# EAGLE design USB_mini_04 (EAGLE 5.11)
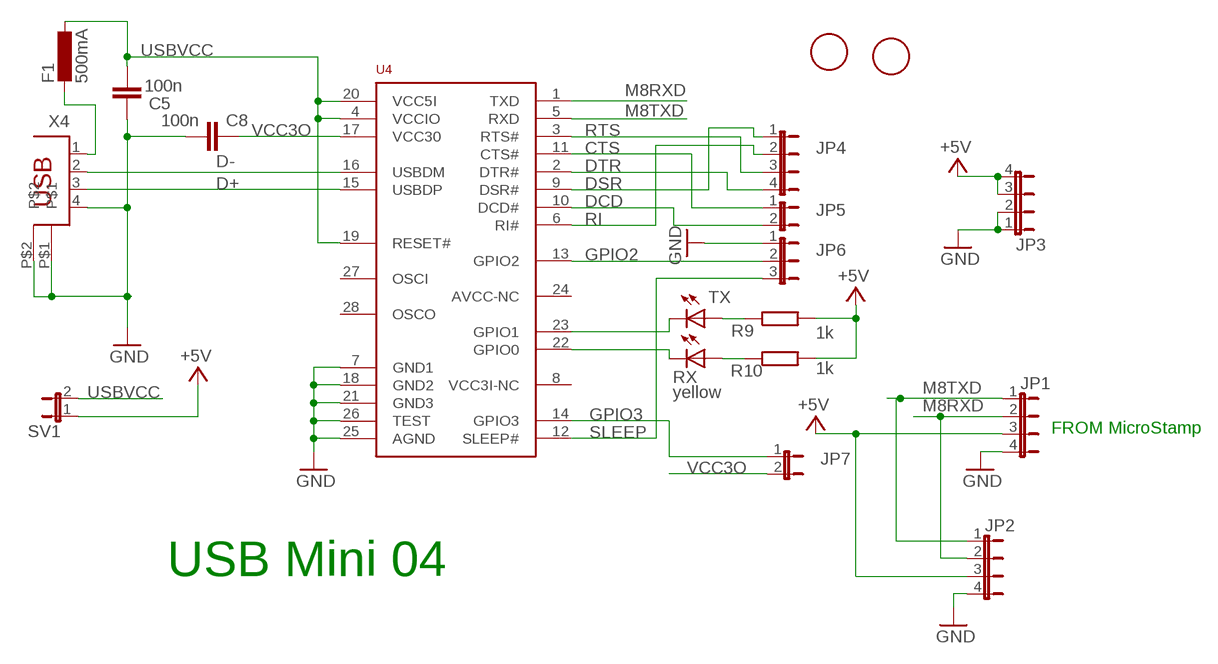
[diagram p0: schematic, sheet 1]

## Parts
C5  100n  C-EUC0805  [C0805]
C8  100n  C-EUC0805  [C0805]
F1  500mA  L-EUL1812  [L1812]
JP1  JP4E  [JP4]
JP2  JP4E  [JP4]
JP3  JP4E  [JP4]
JP4  JP4E  [JP4]
JP5  JP1E  [JP1]
JP6  JP2E  [JP2]
JP7  JP1E  [JP1]
R9  1k  R-EU_R0805  [R0805]
R10  1k  R-EU_R0805  [R0805]
RX  yellow  LEDCHIPLED_0805  [CHIPLED_0805]
SV1  JP1E  [JP1]
TX  yellow  LEDCHIPLED_0805  [CHIPLED_0805]
U4  FT232RL  [SSOP28]
U$1  FIDUCIALMOUNT  [FIDUCIA-MOUNT]
U$2  FIDUCIALMOUNT  [FIDUCIA-MOUNT]
X4  PN61729  [PN61729]

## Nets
+5V [power]: JP1.3 JP2.3 JP3.3 JP3.4 R9.2 R10.2 SV1.1
CTS: JP5.1 U4.11(CTS#)
D+: U4.15(USBDP) X4.3
D-: U4.16(USBDM) X4.2
DCD: JP5.2 U4.10(DCD#)
DSR: JP4.1 U4.9(DSR#)
DTR: JP4.4 U4.2(DTR#)
GND [usbvcc]: C5.2 C8.1 JP1.4 JP2.4 JP3.1 JP3.2 JP6.1 U4.7(GND1) U4.18(GND2) U4.21(GND3) U4.25(AGND) U4.26(TEST) X4.4 X4.P$1 X4.P$2
GPIO2: JP6.2 U4.13(GPIO2)
GPIO3: JP7.1 U4.14(GPIO3)
M8RXD: JP1.2 JP2.2 U4.1(TXD)
M8TXD: JP1.1 JP2.1 U4.5(RXD)
N$2 [usbvcc]: F1.2 X4.1
N$32: TX.C U4.23(GPIO1)
N$34: RX.C U4.22(GPIO0)
N$35: R9.1 TX.A
N$36: R10.1 RX.A
RI: JP4.2 U4.6(RI#)
RTS: JP4.3 U4.3(RTS#)
SLEEP: JP6.3 U4.12(SLEEP#)
USBVCC [usbvcc]: C5.1 F1.1 SV1.2 U4.4(VCCIO) U4.19(RESET#) U4.20(VCC5I)
VCC3O: C8.2 JP7.2 U4.17(VCC30)
Unconnected: U4.8(VCC3I-NC) U4.24(AVCC-NC) U4.27(OSCI) U4.28(OSCO)

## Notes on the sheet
- FROM MicroStamp
- USB Mini 04

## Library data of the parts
C5 C8 = rcl:C-EU: CAPACITOR, European symbol
F1 = rcl:L-EU: INDUCTOR, European symbol
JP1-JP4 = jumper:JP4E: JUMPER
JP5 JP7 SV1 = jumper:JP1E: JUMPER
JP6 = jumper:JP2E: JUMPER
R9 R10 = rcl:R-EU_: RESISTOR, European symbol
RX TX = led:LED: LED
U4 = SmartPrj:FT232RL
U$1 U$2 = SmartPrj:FIDUCIALMOUNT
X4 = SmartPrj:PN61729: BERG USB connector

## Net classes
0 default: width 0.254 mm, clearance 0.254 mm
1 power: width 0.61 mm, clearance 0.254 mm
3 usbvcc: width 0.356 mm, clearance 0.254 mm

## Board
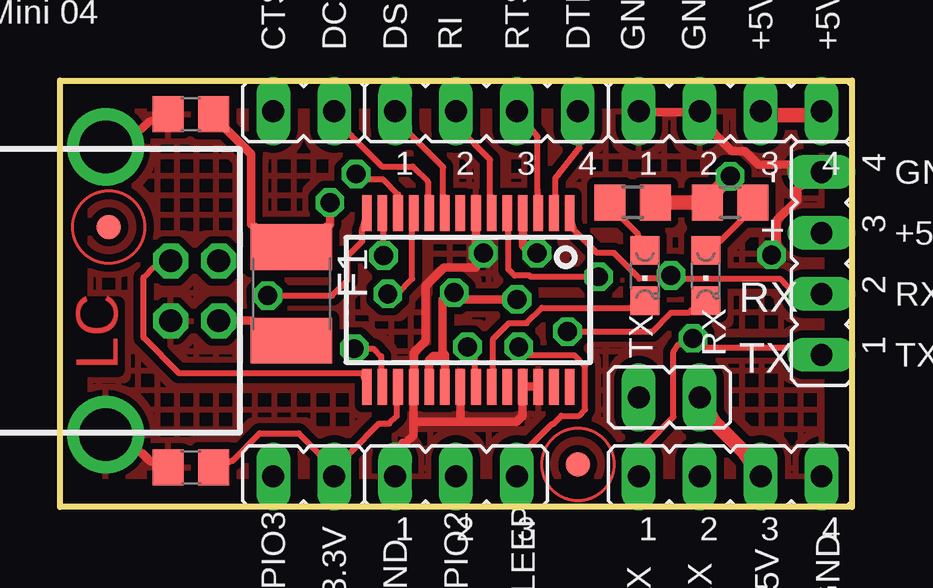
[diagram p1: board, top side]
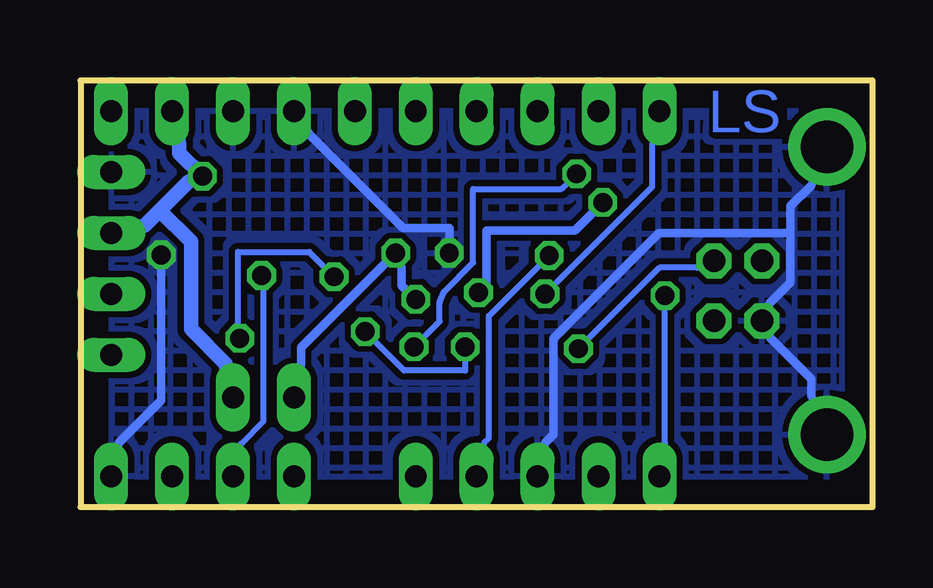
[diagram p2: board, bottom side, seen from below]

Size 33.02 x 17.78 mm. Coordinates in mm from the lower left corner, seen from the top.
Outline: 0,0 0,17.78 33.02,17.78 33.02,0 0,0
Copper layers (1*16): Top 0.035mm / dielectric 1.5mm / Bottom 0.035mm
Design rules "default": minimum track width 10mil, minimum drill 31mil, track to track 10mil, track to pad 10mil, pad to pad 10mil, via to via 16mil, smd to smd 10mil, copper to edge 40mil, drill to drill 10mil, minimum pad ring 10mil, minimum via ring 8mil, stop-mask expansion 4mil, vias tented up to drill 0mil, thermal gap 10mil

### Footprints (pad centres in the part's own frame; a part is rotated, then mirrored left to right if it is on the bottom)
C0805 = smd 1.3 x 1.5: 1 -0.95,0; 2 0.95,0
L1812 = smd 1.9 x 3.4: 1 -1.95,0; 2 1.95,0
JP4 = drill 0.914 long: 1 -3.81,0; 2 -1.27,0; 3 1.27,0; 4 3.81,0
JP1 = drill 0.914 long: 1 0,-1.27; 2 0,1.27
JP2 = drill 0.914 long: 1 -2.54,0; 2 0,0; 3 2.54,0
R0805 = smd 1.3 x 1.5: 1 -0.95,0; 2 0.95,0
CHIPLED_0805 = smd 1.2 x 1.2: A 0,-1.05; C 0,1.05
SSOP28 = smd 0.4 x 1.5: 1 -4.225,-3.625; 2 -3.575,-3.625; 3 -2.925,-3.625; 4 -2.275,-3.625; 5 -1.625,-3.625; 6 -0.975,-3.625; 7 -0.325,-3.625; 8 0.325,-3.625; 9 0.975,-3.625; 10 1.625,-3.625; 11 2.275,-3.625; 12 2.925,-3.625; 13 3.575,-3.625; 14 4.225,-3.625; 15 4.225,3.625; 16 3.575,3.625; 17 2.925,3.625; 18 2.275,3.625; 19 1.625,3.625; 20 0.975,3.625; 21 0.325,3.625; 22 -0.325,3.625; 23 -0.975,3.625; 24 -1.625,3.625; 25 -2.275,3.625; 26 -2.925,3.625; 27 -3.575,3.625; 28 -4.225,3.625
FIDUCIA-MOUNT = smd 1.016 x 1.016: P$1 0,0
PN61729 = drill 0.95 octagon: 1 1.25,4.71; 2 -1.25,4.71; 3 -1.25,2.71; 4 1.25,2.71 | drill 2.2 round: P$1 -6,0; P$2 6,0

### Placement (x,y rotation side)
C5  5.46,16.38 180 top
C8  5.46,1.65 0 top
F1  9.65,8.89 270 top
JP1  31.75,10.16 90 top
JP2  27.94,1.27 0 top
JP3  27.94,16.51 0 top
JP4  17.78,16.51 0 top
JP5  10.16,16.51 270 top
JP6  16.51,1.27 0 top
JP7  10.16,1.27 270 top
R9  23.88,12.7 0 top
R10  27.94,12.7 180 top
RX  26.92,9.65 180 top
SV1  25.4,4.57 90 top
TX  24.38,9.65 180 top
U4  17.02,8.64 180 top
U$1  2.03,11.68 0 top
U$2  21.59,1.78 0 top
X4  1.91,9.02 270 top

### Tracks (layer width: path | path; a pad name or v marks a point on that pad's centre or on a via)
+5V  (via drill 0.79)
  Top 0.61: JP2.3 28.52,2.29 27.3,3.5 SV1.1 | R9.2 R10.2 27.28,13.13 v27.94,13.79 | JP3.4 31.06,16.33 29.9,16.33 JP3.3
  Bottom 0.61: JP3.3 28.91,15.11 28.91,14.76 v27.94,13.79 28.52,13.56 29.72,12.37 | 29.72,12.37 30.35,11.73 JP1.3 | SV1.1 26.98,5.97 28.42,7.42 28.42,11.07 29.72,12.37
CTS  (via drill 0.79)
  Top 0.254: v13.66,8.89 14.05,8.89 14.68,9.53 14.68,11.53 U4.11
  Bottom 0.254: v13.66,8.89 9.2,13.36 9.2,15.11 JP5.1
D+
  Top 0.254: U4.15 12.6,5.59 4.95,5.59 3.48,7.06 3.48,9.58 3.89,9.98 X4.3
D-  (via drill 0.79)
  Top 0.254: v12.27,6.6 13.07,6.6 13.39,6.29 13.39,5.74 U4.16
  Bottom 0.254: v12.27,6.6 8.89,9.98 7.34,9.98 X4.2
DCD
  Top 0.254: U4.10 15.34,13.01 15.34,13.56 14.71,14.2 13.44,14.2 12.14,15.49 12.12,15.49 JP5.2
DSR
  Top 0.254: U4.9 15.98,13.01 15.98,14.17 15.37,14.78 14.66,15.49 JP4.1
DTR
  Top 0.254: U4.2 20.65,13.01 20.65,13.72 21.67,14.99 JP4.4
GND  (via drill 0.79)
  Top 0.356: JP3.1 24.82,16.46 25.98,16.46 JP3.2 27.36,15.49 28.02,14.83 28.55,14.83 29.11,14.28 30.35,14.28 JP1.4 30.73,13.28 30.73,12.8 29.9,11.96 29.9,10.74 v29.67,10.52 | U4.26 19.76,5.03 19.48,5.03 U4.25 19.28,4.27 19.28,3.81 19.02,3.56 16.69,3.56 | 14.73,3.56 14.73,4.27 U4.18 14.76,5.74 14.76,6.45 15.24,6.93 15.24,9.22 16,9.98 17.35,9.98 17.35,10.59 | 14.73,3.56 14.73,2.98 14.41,2.67 14.28,2.67 JP6.1 | 16.69,3.56 16.69,4.27 U4.21 | 14.73,3.56 16.69,3.56 | 17.35,10.59 17.35,11.53 U4.7 | C5.2 3.71,16.08 3.4,15.77 X4.P$1 | C8.1 3.71,1.96 3.4,2.26 X4.P$2 | 17.35,10.59 v17.65,10.59
  Bottom 0.356: v29.67,10.52 29.67,4.45 31.45,2.67 JP2.4 | X4.P$2 2.56,4.62 2.56,5.33 4.29,7.06 X4.4 4.32,8.48 3.43,9.37 3.43,11.43 | 3.43,11.43 3.43,12.55 2.56,13.41 X4.P$1 | JP6.1 13.66,2.67 13.31,3.02 13.31,7.04 8.91,11.43 3.43,11.43 | v17.65,10.59 17.65,11.63 19.58,11.63 23.44,15.49 JP3.1
  pour Top (isolate 0.305, hatched): 0.5,0.5 32.5,0.5 32.5,17.5 0.5,17.5
  pour Bottom (hatched): 0.5,0.5 0.5,17.5 32.5,17.5 32.5,0.5
GPIO2  (via drill 0.79)
  Top 0.254: v13.49,10.49 13.49,11.53 U4.13
  Bottom 0.254: v13.49,10.49 16,7.98 16,2.87 16.2,2.67 JP6.2
GPIO3  (via drill 0.79)
  Top 0.254: v8.66,8.81 11.35,8.81 11.99,9.45 11.99,10.46 12.6,11.07 12.6,11.53 U4.14
  Bottom 0.254: v8.66,8.81 8.66,2.67 JP7.1
M8RXD  (via drill 0.79)
  Top 0.254: 25.48,9.53 30.02,9.53 30.35,9.2 JP1.2 | 25.48,9.53 24.16,9.53 23.09,10.59 22.38,10.59 21.44,11.53 U4.1 | v25.48,9.65 25.48,9.53
  Bottom 0.254: v25.48,9.65 25.4,9.58 25.4,3.58 26.34,2.64 JP2.2
M8TXD  (via drill 0.79)
  Top 0.254: v22.45,9.6 19.63,9.6 19.58,9.65 18.95,9.65 18.69,9.91 18.69,11.53 U4.5 | JP1.1 30.35,6.66 26.77,6.66 v26.39,7.04 25.77,6.76 25.58,6.47 25.58,3.76 24.46,2.64 JP2.1
  Bottom 0.254: v22.45,9.6 23.5,10.64 26.47,10.64 26.47,7.11 v26.39,7.04
N$2
  Top 0.356: X4.1 7.34,7.77 7.98,7.77 F1.2
N$32
  Top 0.254: TX.C 23.77,8.31 20.09,8.31 19.46,7.67 18.72,7.67 18.06,7.01 18.06,5.74 U4.23
N$34  (via drill 0.79)
  Top 0.254: v21.16,7.32 24.69,7.32 25.48,8.1 26.21,8.1 26.31,8.2 RX.C | v16.99,6.68 17.3,6.38 17.3,5.74 U4.22
  Bottom 0.254: v21.16,7.32 19.53,5.69 16.99,5.69 v16.99,6.68
N$35
  Top 0.254: R9.1 23.22,12.27 24.08,11.4 TX.A
N$36
  Top 0.254: RX.A 27.53,11.1 28.65,12.22 R10.1
RI
  Top 0.254: U4.6 17.93,13.01 17.93,14.48 17.3,15.11 16.56,15.88 JP4.2
RTS
  Top 0.254: U4.3 19.89,13.01 19.92,13.05 19.91,13.21 19.91,15.44 JP4.3
SLEEP  (via drill 0.79)
  Top 0.254: v12.34,13.89 12.57,13.66 13.46,13.66 14.1,13.03 14.1,13.01 U4.12 | v19.13,6.68 19.48,6.33 21.44,6.33 21.89,5.87 21.89,4.06 21.64,3.81 20.9,3.81 20.55,3.45 20.5,3.45 19.53,2.49 JP6.3
  Bottom 0.254: v12.34,13.89 12.98,13.26 16.66,13.26 16.66,10.19 17.87,8.97 18.06,8.53 18.06,7.75 v19.13,6.68
USBVCC  (via drill 0.79)
  Top 0.356: C5.1 6.91,15.77 7.98,14.71 7.98,11.79 F1.1 11.25,11.79 v11.25,12.7 | U4.19 15.39,5.99 15.39,6.12 15.57,6.3 15.85,6.3 16.05,6.1 16.05,5.99 U4.20 16.05,6.35 15.95,6.45 15.95,7.42 15.95,8.66 16.43,8.66 | v19.89,10.59 19.62,10.59 19.3,10.91 19.3,11.53 U4.4 | 16.43,8.66 v19.05,8.66 | v16.43,8.94 16.43,8.66
  Bottom 0.356: SV1.2 23.82,5.97 23.82,6.66 v19.89,10.59 19.63,10.01 19.63,9.25 v19.05,8.66 | v11.25,12.7 12.42,11.53 16.1,11.53 16.1,9.27 v16.43,8.94
VCC3O
  Top 0.254: C8.2 7.21,1.96 8.33,3.07 9.96,3.07 10.74,2.29 JP7.2 12.12,2.29 13.31,3.48 13.73,3.48 14.05,3.8 14.05,4.27 U4.17

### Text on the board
Top: LC
Bottom: LS
tPlace: Made in Italy | USB Mini 04 | CTS | DCD | DSR | RI | RTS | DTR | GND | GND | +5V | +5V | - | GND | + | +5V | RX | RX | TX | TX | TX | RX | +5V | GND | GPIO3 | +3.3V | GND | GPIO2 | SLEEP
